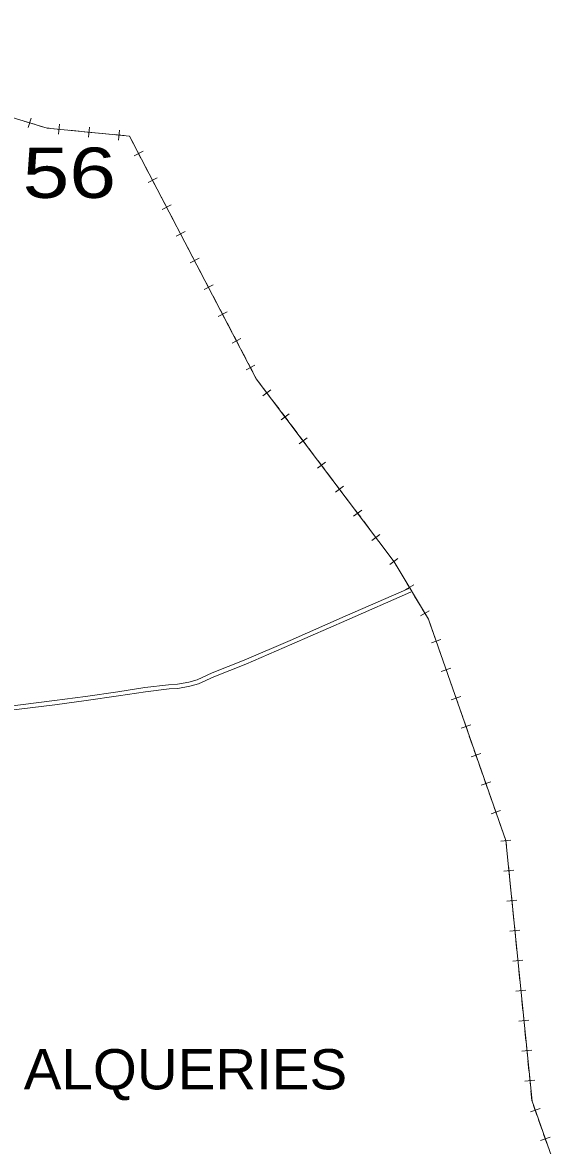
# Model space of a CAD drawing. Extents: x 476989 to 498418, y 4381813 to 4416555.
# Drawn here: x 487128 to 487660, y 4387137 to 4388253 of the extents above; entities that cross this region are included whole.
import ezdxf
from ezdxf.enums import TextEntityAlignment as Align

# ---------------------------------------------------------------- set-up
doc = ezdxf.new("R2010")
doc.units = 0
doc.header["$LTSCALE"] = 20
for name, color, linetype, lineweight in [('34', 7, 'Continuous', 13), ('36', 7, 'Continuous', 13), ('6', 7, 'Continuous', 25)]:
    doc.layers.add(name, color=color, linetype=linetype, lineweight=lineweight)
doc.layers.add('7', color=7, linetype='Continuous')

msp = doc.modelspace()

# ---------------------------------------------------------------- linework, layer by layer
at = {"layer": '34'}
for p, q in [((487136.19, 4388158.03), (487133.28, 4388148.46)), ((487129.95, 4388154.7), (487139.52, 4388151.79)), ((487158.91, 4388147.33), (487168.87, 4388146.35)), ((487164.38, 4388151.82), (487163.4, 4388141.86)), ((487194.22, 4388148.9), (487193.25, 4388138.95)), ((487224.07, 4388145.99), (487223.1, 4388136.04)), ((487173.84, 4388145.87), (487183.8, 4388144.9)), ((487188.76, 4388144.41), (487198.71, 4388143.44)), ((487203.69, 4388142.96), (487213.64, 4388141.99)), ((487218.61, 4388141.5), (487228.56, 4388140.53)), ((487247.48, 4388125.01), (487238.62, 4388120.38)), ((487240.73, 4388127.13), (487245.36, 4388118.26)), ((487247.68, 4388113.83), (487252.31, 4388104.97)), ((487261.37, 4388098.44), (487252.51, 4388093.8)), ((487254.63, 4388100.55), (487259.26, 4388091.69)), ((487261.58, 4388087.26), (487266.21, 4388078.39)), ((487275.27, 4388071.86), (487266.41, 4388067.23)), ((487268.52, 4388073.97), (487273.15, 4388065.11)), ((487275.47, 4388060.68), (487280.1, 4388051.82)), ((487282.42, 4388047.4), (487287.05, 4388038.53)), ((487289.16, 4388045.28), (487280.3, 4388040.65)), ((487289.37, 4388034.1), (487294, 4388025.24)), ((487303.06, 4388018.7), (487294.2, 4388014.07)), ((487296.31, 4388020.82), (487300.94, 4388011.96)), ((487303.26, 4388007.53), (487307.89, 4387998.66)), ((487316.95, 4387992.13), (487308.09, 4387987.49)), ((487310.21, 4387994.24), (487314.84, 4387985.38)), ((487317.16, 4387980.95), (487321.79, 4387972.09)), ((487324.1, 4387967.67), (487328.73, 4387958.8)), ((487330.85, 4387965.55), (487321.99, 4387960.92)), ((487331.05, 4387954.37), (487335.68, 4387945.51)), ((487344.74, 4387938.97), (487335.88, 4387934.34)), ((487338, 4387941.09), (487342.63, 4387932.23)), ((487344.95, 4387927.8), (487349.58, 4387918.93)), ((487358.64, 4387912.4), (487349.78, 4387907.76)), ((487351.89, 4387914.51), (487356.52, 4387905.65)), ((487374.51, 4387888.04), (487366.52, 4387882.02)), ((487367.51, 4387889.02), (487373.52, 4387881.03)), ((487376.53, 4387877.04), (487382.54, 4387869.05)), ((487392.55, 4387864.08), (487384.56, 4387858.06)), ((487385.55, 4387865.06), (487391.56, 4387857.07)), ((487394.57, 4387853.08), (487400.58, 4387845.09)), ((487410.58, 4387840.12), (487402.59, 4387834.1)), ((487403.58, 4387841.1), (487409.6, 4387833.11)), ((487412.6, 4387829.12), (487418.62, 4387821.13)), ((487428.62, 4387816.16), (487420.63, 4387810.14)), ((487421.62, 4387817.14), (487427.63, 4387809.15)), ((487430.64, 4387805.16), (487436.65, 4387797.17)), ((487446.66, 4387792.19), (487438.67, 4387786.18)), ((487439.65, 4387793.18), (487445.67, 4387785.19)), ((487448.67, 4387781.2), (487454.69, 4387773.21)), ((487464.69, 4387768.23), (487456.7, 4387762.22)), ((487457.69, 4387769.22), (487463.7, 4387761.23)), ((487466.71, 4387757.24), (487472.72, 4387749.25)), ((487482.73, 4387744.27), (487474.74, 4387738.26)), ((487475.73, 4387745.26), (487481.74, 4387737.27)), ((487484.75, 4387733.28), (487490.76, 4387725.29)), ((487500.76, 4387720.31), (487492.77, 4387714.3)), ((487501.93, 4387708.74), (487507.05, 4387700.15)), ((487516.46, 4387694.14), (487507.87, 4387689.01)), ((487509.61, 4387695.87), (487514.73, 4387687.28)), ((487517.29, 4387682.99), (487522.41, 4387674.4)), ((487531.82, 4387668.38), (487523.24, 4387663.26)), ((487524.97, 4387670.11), (487530.09, 4387661.52)), ((487532.07, 4387656.96), (487535.37, 4387647.52)), ((487543.39, 4387639.74), (487533.95, 4387636.44)), ((487537.02, 4387642.81), (487540.32, 4387633.37)), ((487541.97, 4387628.65), (487545.28, 4387619.21)), ((487553.3, 4387611.43), (487543.86, 4387608.13)), ((487546.92, 4387614.5), (487550.23, 4387605.06)), ((487551.88, 4387600.34), (487555.18, 4387590.9)), ((487563.2, 4387583.13), (487553.76, 4387579.82)), ((487556.83, 4387586.19), (487560.14, 4387576.76)), ((487561.79, 4387572.04), (487565.09, 4387562.6)), ((487573.11, 4387554.82), (487563.67, 4387551.52)), ((487566.74, 4387557.89), (487570.04, 4387548.45)), ((487571.69, 4387543.73), (487575, 4387534.29)), ((487583.02, 4387526.51), (487573.58, 4387523.21)), ((487576.65, 4387529.58), (487579.95, 4387520.14)), ((487581.6, 4387515.42), (487584.91, 4387505.99)), ((487586.55, 4387501.28), (487589.86, 4387491.84)), ((487592.92, 4387498.21), (487583.49, 4387494.9)), ((487591.51, 4387487.12), (487594.81, 4387477.68)), ((487602.83, 4387469.9), (487593.39, 4387466.6)), ((487596.46, 4387472.97), (487599.76, 4387463.53)), ((487601.42, 4387458.81), (487604.72, 4387449.37)), ((487612.98, 4387440.44), (487603.03, 4387439.44)), ((487609, 4387429.99), (487610, 4387420.04)), ((487615.98, 4387410.6), (487606.03, 4387409.6)), ((487610.5, 4387415.08), (487611.5, 4387405.13)), ((487612, 4387400.15), (487613, 4387390.2)), ((487618.97, 4387380.76), (487609.02, 4387379.76)), ((487613.5, 4387385.24), (487614.5, 4387375.29)), ((487615, 4387370.31), (487615.99, 4387360.36)), ((487616.49, 4387355.4), (487617.49, 4387345.45)), ((487621.97, 4387350.92), (487612.02, 4387349.92)), ((487617.99, 4387340.47), (487618.99, 4387330.52)), ((487624.96, 4387321.08), (487615.01, 4387320.08)), ((487619.49, 4387325.56), (487620.49, 4387315.61)), ((487620.99, 4387310.63), (487621.99, 4387300.68)), ((487627.96, 4387291.24), (487618.01, 4387290.24)), ((487622.48, 4387295.72), (487623.48, 4387285.77)), ((487623.98, 4387280.79), (487624.98, 4387270.84)), ((487625.48, 4387265.88), (487626.48, 4387255.93)), ((487630.95, 4387261.4), (487621, 4387260.4)), ((487626.98, 4387250.95), (487627.98, 4387241)), ((487633.95, 4387231.56), (487624, 4387230.56)), ((487628.48, 4387236.04), (487629.47, 4387226.09)), ((487629.97, 4387221.11), (487630.97, 4387211.16)), ((487636.95, 4387201.72), (487627, 4387200.72)), ((487631.47, 4387206.2), (487632.47, 4387196.25)), ((487632.97, 4387191.27), (487633.97, 4387181.32)), ((487635.56, 4387176.6), (487638.89, 4387167.17)), ((487641.94, 4387173.55), (487632.51, 4387170.22)), ((487640.55, 4387162.46), (487643.89, 4387153.03)), ((487651.93, 4387145.27), (487642.5, 4387141.94)), ((487645.55, 4387148.32), (487648.88, 4387138.89))]:
    msp.add_line(p, q, dxfattribs=at)
for points in [[(486520.9, 4388755.72), (486603, 4388633), (486612, 4388581), (486746, 4388393), (486776, 4388338), (486812, 4388290), (486879, 4388250), (487017, 4388189), (487152, 4388148), (487234, 4388140), (487360, 4387899), (487497, 4387717), (487531, 4387660), (487608, 4387440), (487634, 4387181), (487675, 4387065), (487547, 4387001), (487350, 4386921), (487175, 4386900), (487110, 4386912), (487380, 4386493), (487280.6, 4386441.97)], [(487144.3, 4388150.34), (487152, 4388148), (487153.95, 4388147.81)], [(487233.54, 4388140.04), (487234, 4388140), (487238.42, 4388131.55)], [(487358.84, 4387901.22), (487360, 4387899), (487364.51, 4387893.01)], [(487493.76, 4387721.3), (487497, 4387717), (487499.36, 4387713.04)], [(487606.37, 4387444.66), (487608, 4387440), (487608.51, 4387434.97)]]:
    msp.add_lwpolyline(points, dxfattribs=at)
at = {"layer": '36'}
for points in [[(487109.95, 4387572.95), (487159.3, 4387579.14), (487190.28, 4387583.2), (487222.47, 4387587.83), (487249.22, 4387591.96), (487272.87, 4387594.88), (487281.57, 4387595.35), (487293.04, 4387597.4), (487301.06, 4387599.65), (487316.2, 4387606.51), (487347.8, 4387619.2), (487393.55, 4387638.93), (487448.21, 4387662.97), (487511.52, 4387690.61)], [(486964.24, 4387541.72), (486976.62, 4387544.44), (486997.64, 4387549.32), (487019.8, 4387553.44), (487049.13, 4387558.2), (487065.84, 4387561.49), (487086.71, 4387564.87), (487098.48, 4387566.27), (487110.55, 4387568.8), (487159.87, 4387575), (487190.84, 4387579.06), (487223.09, 4387583.7), (487249.79, 4387587.82), (487273.23, 4387590.72), (487282.06, 4387591.19), (487293.97, 4387593.33), (487302.49, 4387595.71), (487317.85, 4387602.66), (487349.41, 4387615.35), (487395.22, 4387635.1), (487449.89, 4387659.15), (487513.35, 4387686.84), (487513.66, 4387686.96)]]:
    msp.add_lwpolyline(points, dxfattribs=at)

# ---------------------------------------------------------------- texts
at = {"layer": '6', "width": 1.25}
msp.add_text('56', height=50, dxfattribs=at).set_placement((487174.13, 4388078.65), align=Align.CENTER)
at = {"layer": '7', "width": 1.05}
msp.add_text('SES ALQUERIES', height=40, dxfattribs=at).set_placement((487225.58, 4387192.7), align=Align.CENTER)

doc.saveas('drawing.dxf')
